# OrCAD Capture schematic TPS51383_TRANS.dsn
size C; title: TPS51383 4.5-V to 24-V, 8-A Synchronous Buck Converter; rev: 1.0; note: Datasheet: SLUSEE8         EVM: SLUUCG8; note: Synchronous Step Down Converter; note: with 100mA LDO
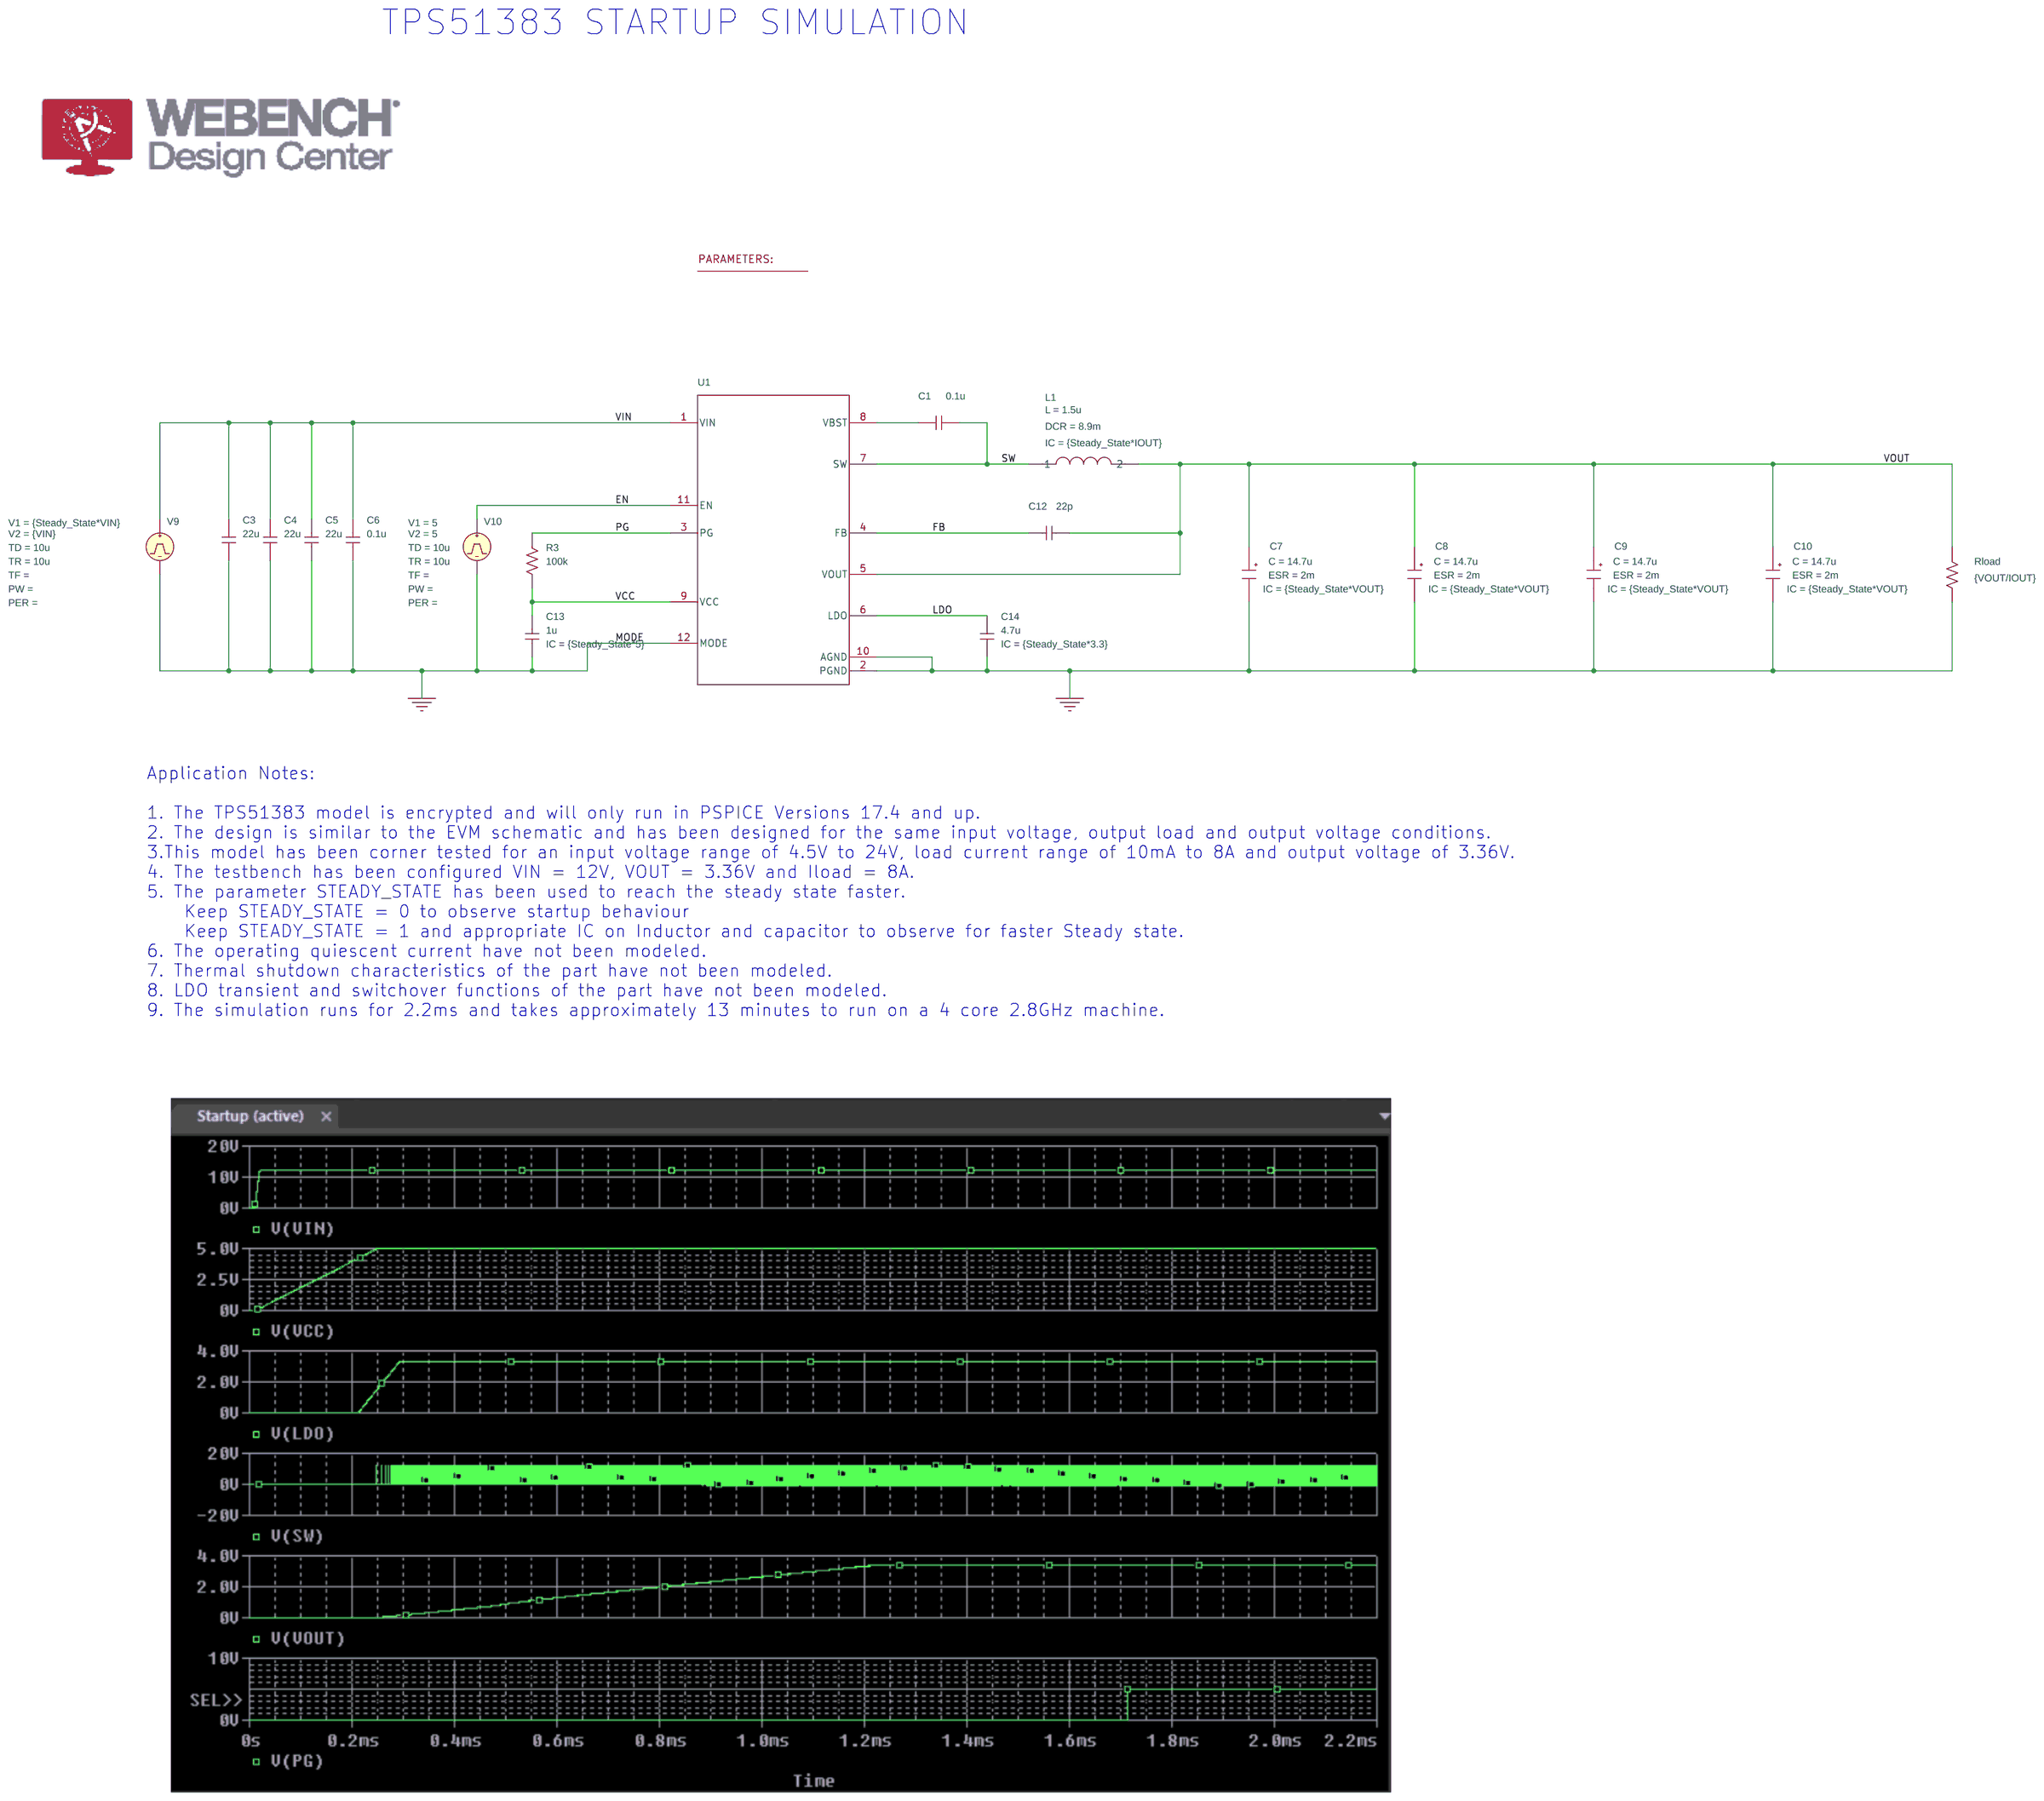
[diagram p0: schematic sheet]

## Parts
3  PARAM
C1  0.1u  [RAD/CK05]
C3  22u  [RAD/CK05]
C4  22u  [RAD/CK05]
C5  22u  [RAD/CK05]
C6  0.1u  [RAD/CK05]
C7  CESR
C8  CESR
C9  CESR
C10  CESR
C12  22p  [RAD/CK05]
C13  1u  [RAD/CK05]
C14  4.7u  [RAD/CK05]
L1  LDCR
R3  100k  [AX/RC05]
Rload  {VOUT/IOUT}  [AX/RC05]
U1  Value  [RJN0012A-MFG]
V9  VPULSE
V10  VPULSE

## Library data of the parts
3 = PARAM: IOUT: 8; Steady_State: 0; VIN: 12; VOUT: 3.36
C1 = C: IC: 0
C3-C6 = C: IC: {Steady_State*VIN}
C7-C10 = CESR_0: C: 14.7u; ESL: 0; ESR: 2m; IC: {Steady_State*VOUT}
C12 = C: IC: {Steady_State*2.76}
C13 = C: IC: {Steady_State*5}
C14 = C: IC: {Steady_State*3.3}
L1 = LDCR: DCR: 8.9m; IC: {Steady_State*IOUT}; L: 1.5u
R3 Rload = R
U1 = TPS51383RJN_TRANS
V9 = VPULSE: TD: 10u; TR: 10u; V1: {Steady_State*VIN}; V2: {VIN}
V10 = VPULSE: TD: 10u; TR: 10u; V1: 5; V2: 5

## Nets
VCC: C13.2 R3.2 U1.9(VCC)
VIN: C3.1 C4.1 C5.1 C6.1 U1.1(VIN) V9.1(+)
0: C3.2 C4.2 C5.2 C6.2 C7.2(OUT) C8.2(OUT) C9.2(OUT) C10.2(OUT) C13.1 C14.1 Rload.2 U1.2(PGND) U1.10(AGND) U1.12(MODE) V9.2(-) V10.2(-)
EN: U1.11(EN) V10.1(+)
FB: C12.2 U1.4(FB)
LDO: C14.2 U1.6(LDO)
PG: R3.1 U1.3(PG)
SW: C1.1 L1.1 U1.7(SW)
VOUT: C7.1(IN) C8.1(IN) C9.1(IN) C10.1(IN) C12.1 L1.2 Rload.1 U1.5(VOUT)
N16798746: C1.2 U1.8(VBST)

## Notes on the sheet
- TPS51383 STARTUP SIMULATION
- Application Notes:
  1. The TPS51383 model is encrypted and will only run in PSPICE Versions 17.4 and up.
  2. The design is similar to the EVM schematic and has been designed for the same input voltage, output load and output voltage conditions.
  3.This model has been corner tested for an input voltage range of 4.5V to 24V, load current range of 10mA to 8A and output voltage of 3.36V.
  4. The testbench has been configured VIN = 12V, VOUT = 3.36V and Iload = 8A.
  5. The parameter STEADY_STATE has been used to reach the steady state faster.
      Keep STEADY_STATE = 0 to observe startup behaviour
      Keep STEADY_STATE = 1 and appropriate IC on Inductor and capacitor to observe for faster Steady state.
  6. The operating quiescent current have not been modeled.
  7. Thermal shutdown characteristics of the part have not been modeled.
  8. LDO transient and switchover functions of the part have not been modeled.
  9. The simulation runs for 2.2ms and takes approximately 13 minutes to run on a 4 core 2.8GHz machine.
